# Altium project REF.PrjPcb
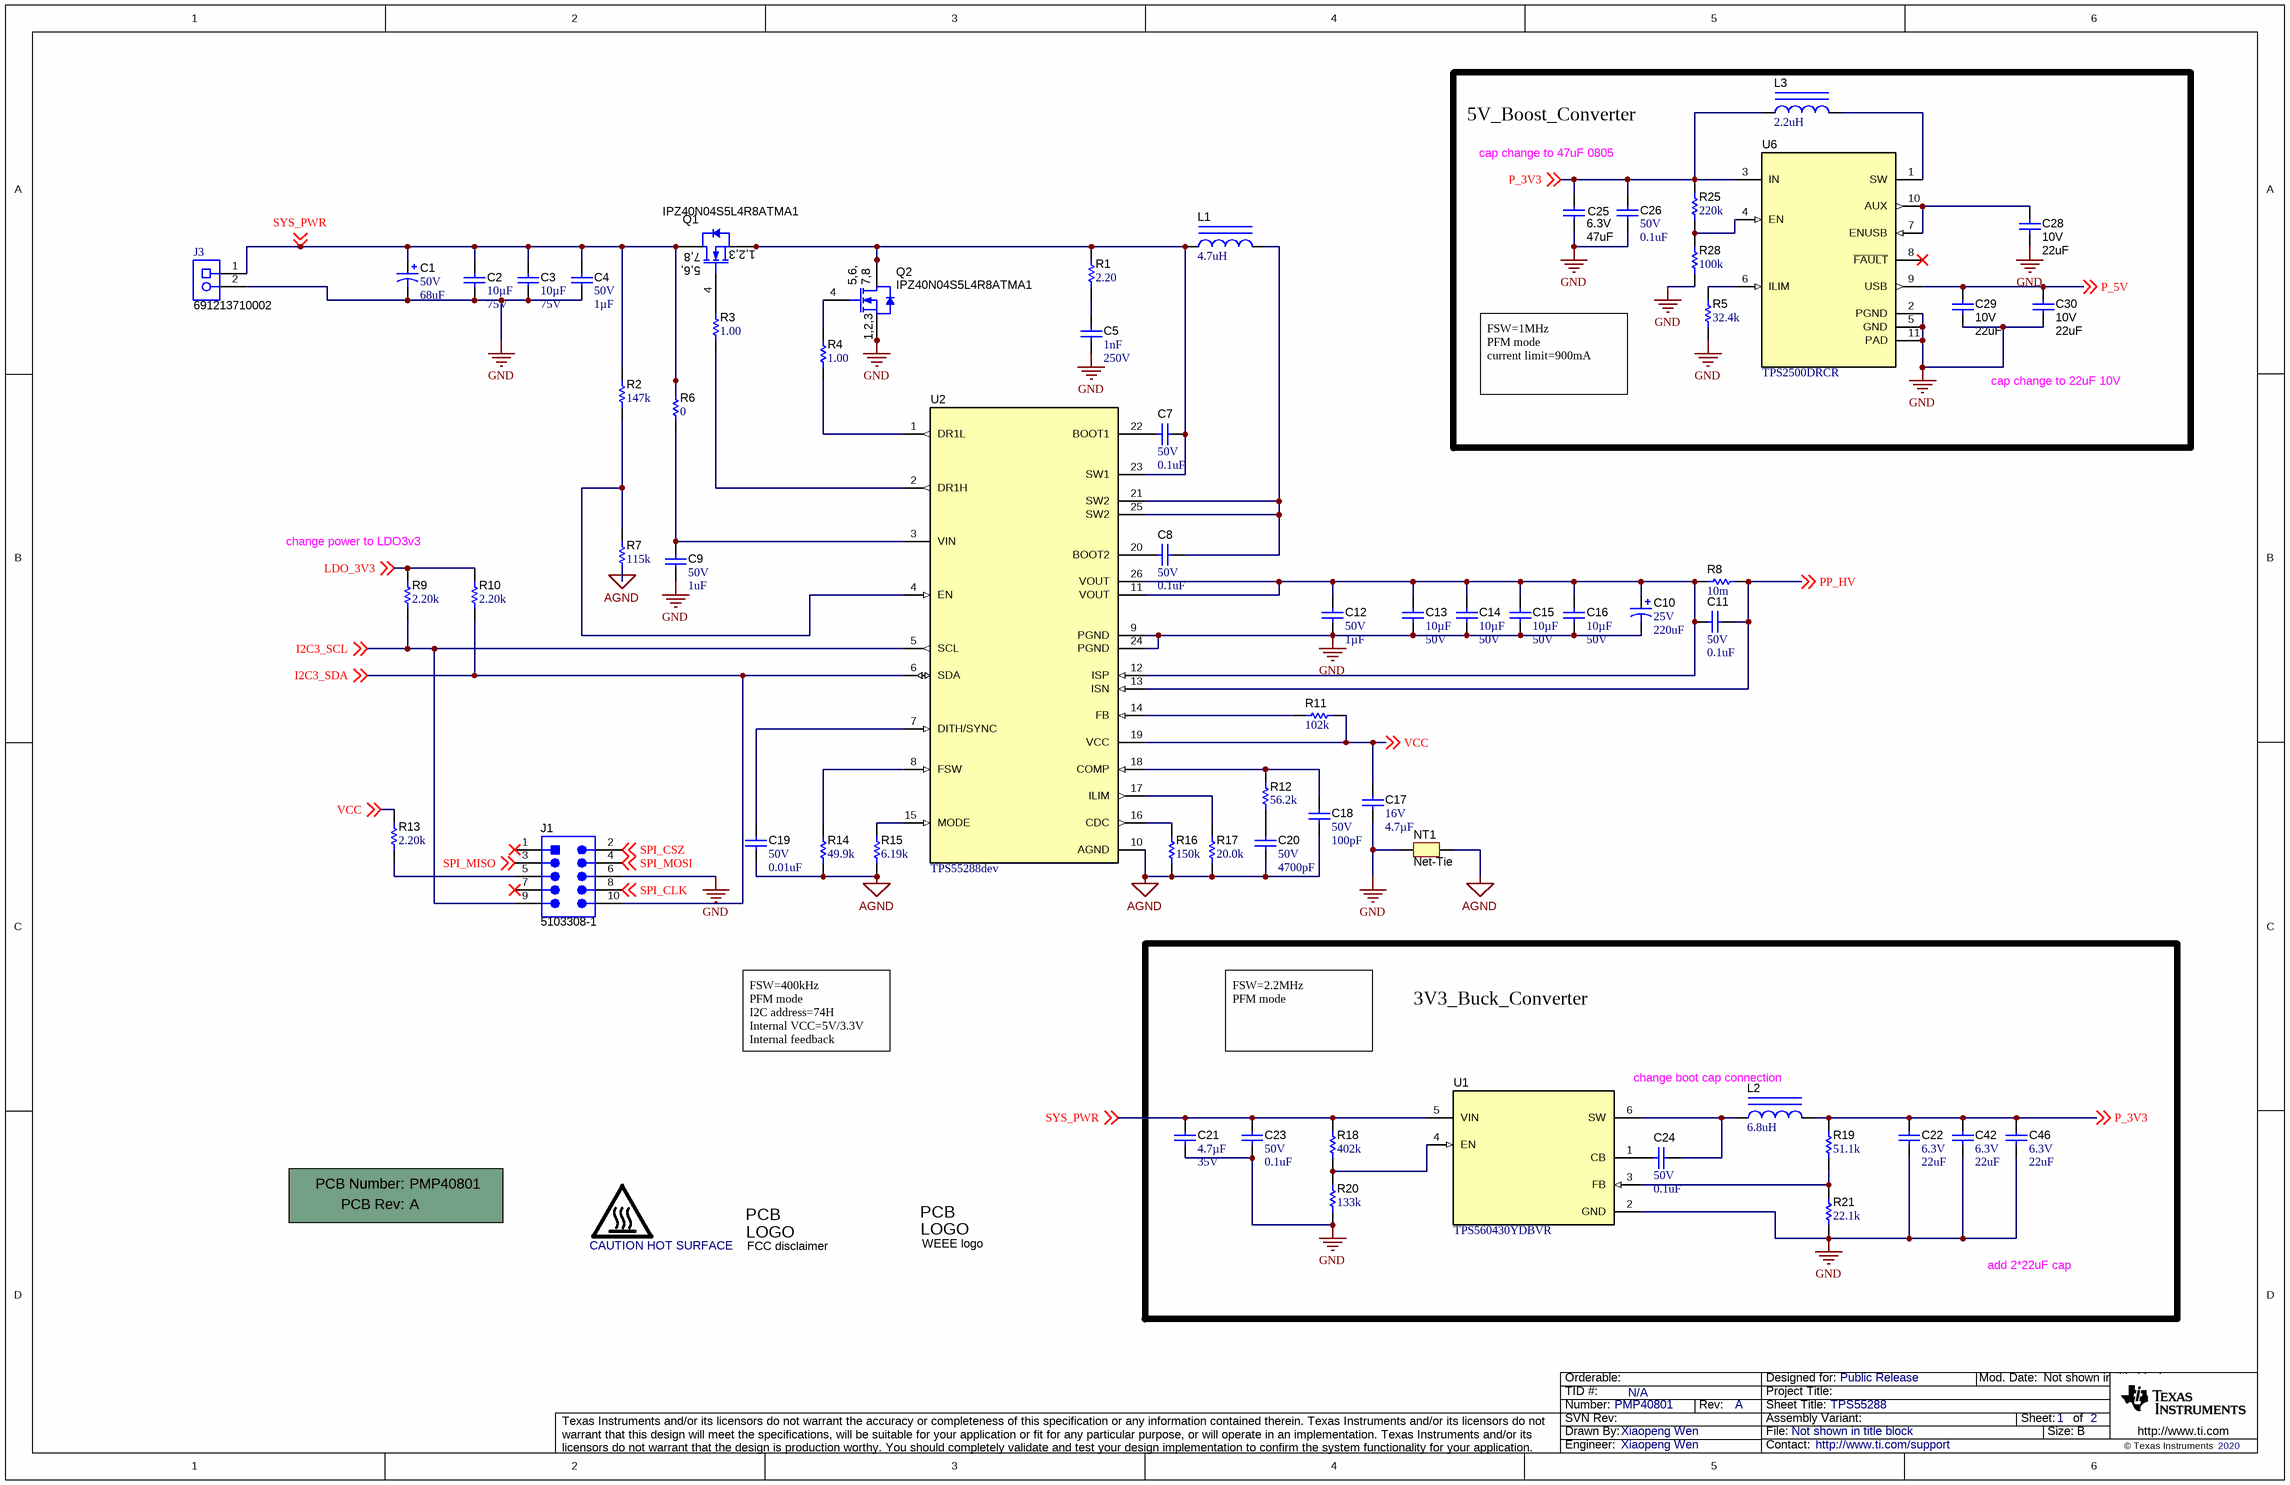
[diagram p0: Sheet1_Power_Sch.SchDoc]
TID: N/A; TechSupport: http://www.ti.com/support; SCH_Rev: A; PRJ_Number: PMP40801; PRJ_Engineer: Xiaopeng Wen; PRJ_Customer: Public Release; PCB_Rev: A; PCB_LayoutX: Xiaopeng Wen; CopyrightYear: 2020
2 sheets, 110 parts. Net scope: global (net labels, ports and power ports of the same name join across sheets).
Board file: REF0324.PcbDoc
Sheets:
  Sheet1_Power_Sch.SchDoc
  Sheet2_PD_Sch.SchDoc

## Sheet Sheet1_Power_Sch.SchDoc: TPS55288
size 431 x 279 mm; Date: Not shown in title block; ApprovedBy: Not shown in title block; CheckedBy: Not shown in title block; Author: Not shown in title block; CompanyName: Not shown in title block; DrawnBy: Xiaopeng Wen; Engineer: Not shown in title block; Organization: Not shown in title block; Address1: Not shown in title block; Address2: Not shown in title block; Address3: Not shown in title block; Address4: Not shown in title block; DocumentNumber: 1; Revision: Use project parameter SCH_Rev; SheetNumber: 1; SheetTotal: 2; PageSetup: Record=PageOptions¦CenterHorizontal=True¦CenterVertical=True¦PrintScale=1.00¦XCorrection=1.00¦YCorrection=1.00¦PrintKind=0¦BorderSize=5000000¦LeftOffset=0¦BottomOffset=0¦Orientation=2¦PaperLength=1000¦PaperWidth=1000¦Scale=100¦PaperSource=15¦PrintQuality=600¦MediaType=1¦DitherType=10¦PrintScaleMode=1¦PaperKind=Letter

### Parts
!PCB1  Printed Circuit Board  (value not drawn)  (mechanical)
C1  VDC_V: 50V  ValueDisplayed: 68uF  [SM_RADIAL_8MM]  (hidden comment: EEHZA1H680P)
C2  ValueDisplayed: 10µF  VDC_V: 75V  [1210_280]  (hidden comment: CGA6P1X7R1N106M250AC)
C3  ValueDisplayed: 10µF  VDC_V: 75V  [1210_280]  (hidden comment: CGA6P1X7R1N106M250AC)
C4  VDC_V: 50V  ValueDisplayed: 1µF  [0603]  (hidden comment: GRT188R61H105ME13D)
C5  Cap_F: 1nF  VDC_V: 250V  [0805_HV]  (hidden comment: GRM21AR72E222KW01D)
C7  VDC_V: 50V  ValueDisplayed: 0.1uF  [0402]  (hidden comment: CGA2B3X7R1H104K050BB)
C8  VDC_V: 50V  ValueDisplayed: 0.1uF  [0402]  (hidden comment: CGA2B3X7R1H104K050BB)
C9  VDC_V: 50V  ValueDisplayed: 1uF  [0402]  (hidden comment: CGA2B3X7R1H103K050BB)
C10  VDC_V: 25V  ValueDisplayed: 220uF  [SM_RADIAL_8MM]  (hidden comment: EEHZA1E221P)
C11  VDC_V: 50V  ValueDisplayed: 0.1uF  [0402]  (hidden comment: CGA2B3X7R1H104K050BB)
C12  VDC_V: 50V  ValueDisplayed: 1µF  [0603]  (hidden comment: GRT188R61H105ME13D)
C13  ValueDisplayed: 10µF  VDC_V: 50V  [1206_190]  (hidden comment: CGA5L1X7R1H106K160AC)
C14  ValueDisplayed: 10µF  VDC_V: 50V  [1206_190]  (hidden comment: CGA5L1X7R1H106K160AC)
C15  ValueDisplayed: 10µF  VDC_V: 50V  [1206_190]  (hidden comment: CGA5L1X7R1H106K160AC)
C16  ValueDisplayed: 10µF  VDC_V: 50V  [1206_190]  (hidden comment: CGA5L1X7R1H106K160AC)
C17  VDC_V: 16V  ValueDisplayed: 4.7µF  [0603]  (hidden comment: GRT188R61C475KE13D)
C18  VDC_V: 50V  ValueDisplayed: 100pF  [0402]  (hidden comment: CGA2B2C0G1H101J050BA)
C19  VDC_V: 50V  ValueDisplayed: 0.01uF  [0402]  (hidden comment: CGA2B3X7R1H103K050BB)
C20  VDC_V: 50V  ValueDisplayed: 4700pF  [0402]  (hidden comment: CGA2B2X7R1H472K050BA)
C21  Cap_F: 4.7µF  VDC_V: 35V  [0805_HV]  (hidden comment: C2012X7R1V475K125AC)
C22  VDC_V: 6.3V  ValueDisplayed: 22uF  [0805_HV]  (hidden comment: GRM21BD70J226ME44L)
C23  VDC_V: 50V  ValueDisplayed: 0.1uF  [0402]  (hidden comment: GCM155R71H104KE02D)
C24  VDC_V: 50V  ValueDisplayed: 0.1uF  [0402]  (hidden comment: GCM155R71H104KE02D)
C25  VDC_V: 6.3V  ValueDisplayed: 47uF  [0805L]  (hidden comment: GRM21BR60J476ME15L)
C26  VDC_V: 50V  ValueDisplayed: 0.1uF  [0402]  (hidden comment: GCM155R71H104KE02D)
C28  VDC_V: 10V  ValueDisplayed: 22uF  [0603]  (hidden comment: C1608X5R1A226M080AC)
C29  VDC_V: 10V  ValueDisplayed: 22uF  [0603]  (hidden comment: C1608X5R1A226M080AC)
C30  VDC_V: 10V  ValueDisplayed: 22uF  [0603]  (hidden comment: C1608X5R1A226M080AC)
C42  VDC_V: 6.3V  ValueDisplayed: 22uF  [0805_HV]  (hidden comment: GRM21BD70J226ME44L)
C46  VDC_V: 6.3V  ValueDisplayed: 22uF  [0805_HV]  (hidden comment: GRM21BD70J226ME44L)
J1  5103308-1  [CONN_5103308-1]
J3  691213710002  [Wurth_691213710002]
L1  ValueDisplayed: 4.7uH  [XAL1010]  (hidden comment: XAL1010-472MEB)
L2  ValueDisplayed: 6.8uH  [ME3220]  (hidden comment: ME3220-682MLB)
L3  ValueDisplayed: 2.2uH  [WE-MAIA_4020]  (hidden comment: 78438356022)
Logo1  FCC disclaimer  [FCC_disclaimer]  (no BOM)
Logo2  WEEE logo  [WEEE_Minimum]  (no BOM)
LOGO3  CAUTION HOT SURFACE  [IEC_HotSurface_Small]  (no BOM)
NT1  Net-Tie  [Net-Tie_10milWide_30milLong]  (net tie, no BOM)
Q1  IPZ40N04S5L4R8ATMA1  [PG-TSDSON-8-32]
Q2  IPZ40N04S5L4R8ATMA1  [PG-TSDSON-8-32]
R1  ValueDisplayed: 2.20  [1206]  (hidden comment: ERJ-8RQF2R2V)
R2  ValueDisplayed: 147k  [0402]  (hidden comment: CRCW0402100KFKED)
R3  ValueDisplayed: 1.00  [0402]  (hidden comment: CRCW06031R00FKEA)
R4  ValueDisplayed: 1.00  [0402]  (hidden comment: CRCW06031R00FKEA)
R5  ValueDisplayed: 32.4k  [0402]  (hidden comment: CRCW040232K4FKED)
R6  ValueDisplayed: 0  [0402]  (hidden comment: CRCW04020000Z0ED)
R7  ValueDisplayed: 115k  [0402]  (hidden comment: CRCW0402115KFKED)
R8  ValueDisplayed: 10m  [FP-CRF1206-FZ-R010ELF_1206-MFG]  (hidden comment: CRF1206-FZ-R010ELF)
R9  ValueDisplayed: 2.20k  [0402]  (hidden comment: CRCW04022K20FKED)
R10  ValueDisplayed: 2.20k  [0402]  (hidden comment: CRCW04022K20FKED)
R11  ValueDisplayed: 102k  [0402]  (hidden comment: CRCW0402102KFKED)
R12  ValueDisplayed: 56.2k  [0402]  (hidden comment: CRCW040256K2FKED)
R13  ValueDisplayed: 2.20k  [0402]  (hidden comment: CRCW04022K20FKED)
R14  ValueDisplayed: 49.9k  [0402]  (hidden comment: CRCW040249K9FKED)
R15  ValueDisplayed: 6.19k  [0402]  (hidden comment: CRCW04026K19FKED)
R16  ValueDisplayed: 150k  [0402]  (hidden comment: CRCW0402150KFKED)
R17  ValueDisplayed: 20.0k  [0402]  (hidden comment: CRCW040220K0FKED)
R18  ValueDisplayed: 402k  [0402]  (hidden comment: CRCW0402100KFKED)
R19  ValueDisplayed: 51.1k  [0402]  (hidden comment: CRCW040251K1FKED)
R20  ValueDisplayed: 133k  [0402]  (hidden comment: CRCW0402100KFKED)
R21  ValueDisplayed: 22.1k  [0402]  (hidden comment: CRCW040222K1FKED)
R25  ValueDisplayed: 220k  [0402]  (hidden comment: CRCW0402100KFKED)
R28  ValueDisplayed: 100k  [0402]  (hidden comment: CRCW0402100KFKED)
U1  TPS560430YDBVR  [DBV0006A_N]
U2  TPS55288dev  [RPM0026A]
U6  TPS2500DRCR  [DRC0010J]

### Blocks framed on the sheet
5V_Boost_Converter: C25 C26 C28-C30 L3 R5 R25 R28 U6
3V3_Buck_Converter: C21-C24 C42 C46 L2 R18-R21 U1

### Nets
AGND: C18.2 C19.2 C20.2 NT1.2 R7.1 R14.1 R15.1 R16.1 R17.1 U2.10(AGND)
GND: C1.2(-) C2.2 C3.2 C4.2 C5.2 C9.2 C10.2(-) C12.2 C13.2 C14.2 C15.2 C16.2 C17.2 C21.2 C22.2 C23.2 C25.2 C26.2 C28.2 C29.2 C30.2 C42.2 C46.2 J1.6 J3.2 NT1.1 Q2.1(S) Q2.2(S) Q2.3(S) R5.1 R20.1 R21.1 R28.1 U1.2(GND) U2.9(PGND) U2.24(PGND) U6.2(PGND) U6.5(GND) U6.11(PAD)
I2C3_SCL: J1.9 R9.1 U2.5(SCL) ; off-sheet I2C3_SCL
I2C3_SDA: J1.10 R10.1 U2.6(SDA) ; off-sheet I2C3_SDA
LDO_3V3: R9.2 R10.2 ; off-sheet LDO_3V3
P_3V3: C22.1 C25.1 C26.1 C42.1 C46.1 L2.2 L3.1 R19.2 R25.2 U6.3(IN) ; off-sheet P_3V3
P_5V: C29.1 C30.1 U6.9(USB) ; off-sheet P_5V
PP_HV: C11.2 R8.2 U2.13(ISN) ; off-sheet PP_HV
SPI_CLK: J1.8 ; off-sheet SPI_CLK
SPI_CSZ: J1.2 ; off-sheet SPI_CSZ
SPI_MISO: J1.3 ; off-sheet SPI_MISO
SPI_MOSI: J1.4 ; off-sheet SPI_MOSI
SYS_PWR: C1.1(+) C2.1 C3.1 C4.1 C21.1 C23.1 J3.1 Q1.5(D) Q1.6(D) Q1.7(D) Q1.8(D) Q1.9(D) R2.2 R6.2 R18.2 U1.5(VIN) ; off-sheet SYS_PWR
VCC: C17.1 R11.1 R13.2 U2.19(VCC) ; off-sheet VCC
NetC5_1: C5.1 R1.1
NetC7_1: C7.1 U2.22(BOOT1)
NetC7_2: C7.2 L1.1 Q1.1(S) Q1.2(S) Q1.3(S) Q2.5(D) Q2.6(D) Q2.7(D) Q2.8(D) Q2.9(D) R1.2 U2.23(SW1)
NetC8_1: C8.1 U2.20(BOOT2)
NetC8_2: C8.2 L1.2 U2.21(SW2) U2.25(SW2)
NetC9_1: C9.1 R6.1 U2.3(VIN)
NetC10_1: C10.1(+) C11.1 C12.1 C13.1 C14.1 C15.1 C16.1 R8.1 U2.11(VOUT) U2.12(ISP) U2.26(VOUT)
NetC18_1: C18.1 R12.2 U2.18(COMP)
NetC19_1: C19.1 U2.7(DITH/SYNC)
NetC20_1: C20.1 R12.1
NetC24_1: C24.1 U1.1(CB)
NetC24_2: C24.2 L2.1 U1.6(SW)
NetC28_1: C28.1 U6.7(ENUSB) U6.10(AUX)
NetJ1_5: J1.5 R13.1
NetL3_2: L3.2 U6.1(SW)
NetQ1_4: Q1.4(G) R3.2
NetQ2_4: Q2.4(G) R4.2
NetR2_1: R2.1 R7.2 U2.4(EN)
NetR3_1: R3.1 U2.2(DR1H)
NetR4_1: R4.1 U2.1(DR1L)
NetR5_2: R5.2 U6.6(ILIM)
NetR11_2: R11.2 U2.14(FB)
NetR14_2: R14.2 U2.8(FSW)
NetR15_2: R15.2 U2.15(MODE)
NetR16_2: R16.2 U2.16(CDC)
NetR17_2: R17.2 U2.17(ILIM)
NetR18_1: R18.1 R20.2 U1.4(EN)
NetR19_1: R19.1 R21.2 U1.3(FB)
NetR25_1: R25.1 R28.2 U6.4(EN)

Not connected (* = marked no-connect by the designer): J1 1* 7*; U6 8(~{FAULT})*

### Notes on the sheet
- cap change to 47uF 0805
- FSW=1MHz
  PFM mode
  current limit=900mA
- cap change to 22uF 10V
- (near R9) change power to LDO3v3
- FSW=400kHz
  PFM mode
  I2C address=74H
  Internal VCC=5V/3.3V
  Internal feedback
- FSW=2.2MHz
  PFM mode
- change boot cap connection
- add 2*22uF cap

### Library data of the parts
!PCB1 = CMP-0003618-2: Manufacturer: Any; PartNumber: PMP40801
C1 = CMP-0012579-3: CAP, Polymer Hybrid, 68 uF, 50 V, +/- 20%, 30 ohm, 8x10 SMD; Manufacturer: Panasonic; TaMin_C: -55°C; ESR_ohm: 30; Polarized: Y; SizeAreaWB_mm2: 113.3; Value1: 30 ohm; Value: 68uF; TaMax_C: 105°C; SizeZ_mm: 10.2; SizeX_mm: 9; SizeY_mm: 8.3; SizeArea_mm2: 74.7; CompType: Capacitor; Cap_F: 68µF; IRMS_A: 1.8A; AEC Category: Q200
C2 C3 = CMP-0085951-1: CAP, CERM, 10 µF, 75 V,+/- 20%, X7R, AEC-Q200 Grade 1, 1210; Manufacturer: TDK; SizeX_mm: 3.2; Cap_Case: 1210; AEC Qualified: Y; Polarized: N; AEC Category: Q200; U/M: EA; SizeZ_mm: 2.8; SizeY_mm: 2.5; TaMin_C: -55°C; AEC Grade: 1; SizeAreaWB_mm2: 14.7; SizeArea_mm2: 8; TaMax_C: 125°C; Value: 10uF
C4 C12 = CMP-0081784-1: CAP, CERM, 1 µF, 50 V,+/- 20%, X5R, AEC-Q200 Grade 3, 0603; Manufacturer: MuRata; TaMin_C: -55°C; Polarized: N; SizeAreaWB_mm2: 4.68; U/M: EA; Value: 1uF; TaMax_C: 85°C; SizeZ_mm: 1; SizeX_mm: 1.6; SizeY_mm: 0.8; SizeArea_mm2: 1.28; AEC Qualified: Y; AEC Grade: 3; AEC Category: Q200
C5 = CMP-0008253-2: CAP, CERM, 2200 pF, 250 V, +/- 10%, X7R, 0805; Manufacturer: MuRata; TaMin_C: -55°C; Polarized: N; SizeAreaWB_mm2: 6.75; Value1: Unknown; U/M: EA; Value: 2200pF; TaMax_C: 125°C; SizeZ_mm: 1.45; SizeX_mm: 2; SizeY_mm: 1.25; Cap_Case: 0805; SizeArea_mm2: 2.5; CompType: Capacitor; AEC Category: Q200
C7 C8 C11 = CMP-0006325-2: CAP, CERM, 0.1 uF, 50 V, +/- 10%, X7R, AEC-Q200 Grade 1, 0402; Manufacturer: TDK; TaMin_C: -55°C; ESR_ohm: 0.039064; Polarized: N; SizeAreaWB_mm2: 3; Value1: 0.039064 ohm; U/M: EA; Value: 0.1uF; TaMax_C: 125°C; SizeZ_mm: 0.6; SizeX_mm: 1; SizeY_mm: 0.5; AEC Qualified: Y; Cap_F: 100nF; IRMS_A: 8.14669dA; AEC Category: Q200
C9 = CMP-0006324-2: CAP, CERM, 1 uF, 50 V, +/- 10%, X7R, AEC-Q200 Grade 1, 0402; Manufacturer: TDK; TaMin_C: -55°C; ESR_ohm: 3.33065d; Polarized: N; SizeAreaWB_mm2: 3; Value1: 0.333065 ohm; U/M: EA; Value: 1uF; TaMax_C: 125°C; SizeZ_mm: 0.6; SizeX_mm: 1; SizeY_mm: 0.5; CompType: Capacitor; AEC Qualified: Y; Cap_F: 10nF; IRMS_A: 3.23373dA; AEC Category: Q200
C10 = CMP-0012571-3: CAP, Polymer Hybrid, 220 uF, 25 V, +/- 20%, 27 ohm, 8x10 SMD; Manufacturer: Panasonic; TaMin_C: -55°C; ESR_ohm: 27; Polarized: Y; SizeAreaWB_mm2: 113.3; Value1: 27 ohm; Value: 220uF; TaMax_C: 105°C; SizeZ_mm: 10.2; SizeX_mm: 9; SizeY_mm: 8.3; SizeArea_mm2: 74.7; CompType: Capacitor; Cap_F: 220µF; IRMS_A: 2.3A; AEC Category: Q200
C13-C16 = CMP-0085950-1: CAP, CERM, 10 µF, 50 V,+/- 10%, X7R, AEC-Q200 Grade 1, 1206; Manufacturer: TDK; SizeZ_mm: 1.9; Value: 10uF; Cap_Case: 1206; AEC Grade: 1; TaMin_C: -55°C; U/M: EA; SizeArea_mm2: 5.12; TaMax_C: 125°C; AEC Qualified: Y; AEC Category: Q200; SizeX_mm: 3.2; SizeY_mm: 1.6; Polarized: N; SizeAreaWB_mm2: 10.92
C17 = CMP-0081052-1: CAP, CERM, 4.7 µF, 16 V,+/- 10%, X5R, AEC-Q200 Grade 3, 0603; Manufacturer: MuRata; SizeAreaWB_mm2: 4.68; SizeArea_mm2: 1.28; AEC Qualified: Y; AEC Category: Q200; Value: 4.7uF; TaMax_C: 85°C; SizeZ_mm: 1; AEC Grade: 3; Polarized: N; TaMin_C: -55°C; SizeY_mm: 0.8; U/M: EA; SizeX_mm: 1.6
C18 = CMP-0006308-2: CAP, CERM, 100 pF, 50 V, +/- 5%, C0G/NP0, AEC-Q200 Grade 1, 0402; Manufacturer: TDK; TaMin_C: -55°C; Polarized: N; SizeAreaWB_mm2: 3; Value1: Unknown; U/M: EA; Value: 100pF; TaMax_C: 125°C; SizeZ_mm: 0.6; SizeX_mm: 1; SizeY_mm: 0.5; AEC Qualified: Y; AEC Category: Q200
C19 = CMP-0006324-2: CAP, CERM, 0.01 uF, 50 V, +/- 10%, X7R, AEC-Q200 Grade 1, 0402; Manufacturer: TDK; TaMin_C: -55°C; ESR_ohm: 3.33065d; Polarized: N; SizeAreaWB_mm2: 3; Value1: 0.333065 ohm; U/M: EA; Value: 0.01uF; TaMax_C: 125°C; SizeZ_mm: 0.6; SizeX_mm: 1; SizeY_mm: 0.5; AEC Qualified: Y; Cap_F: 10nF; IRMS_A: 3.23373dA; AEC Category: Q200
C20 = CMP-0006321-2: CAP, CERM, 4700 pF, 50 V, +/- 10%, X7R, AEC-Q200 Grade 1, 0402; Manufacturer: TDK; TaMin_C: -55°C; ESR_ohm: 4.13508d; Polarized: N; SizeAreaWB_mm2: 3; Value1: 0.413508 ohm; U/M: EA; Value: 4700pF; TaMax_C: 125°C; SizeZ_mm: 0.6; SizeX_mm: 1; SizeY_mm: 0.5; AEC Qualified: Y; Cap_F: 4.7nF; IRMS_A: 3.30878dA; AEC Category: Q200
C21 = CMP-0007885-2: CAP, CERM, 4.7 uF, 35 V, +/- 10%, X7R, 0805; Manufacturer: TDK; TaMin_C: -55°C; ESR_ohm: 2.346m; Polarized: N; SizeAreaWB_mm2: 6.75; Value1: 0.002346 ohm; U/M: EA; Value: 4.7uF; TaMax_C: 125°C; SizeZ_mm: 1.45; SizeX_mm: 2; SizeY_mm: 1.25; Cap_Case: 0805; SizeArea_mm2: 2.5; IRMS_A: 4.26021A; AEC Category: Q200
C22 C42 C46 = CMP-0008274-1: CAP, CERM, 22 uF, 6.3 V, +/- 20%, X7T, 0805; Manufacturer: MuRata; TaMin_C: -55°C; Polarized: N; SizeAreaWB_mm2: 6.75; Value1: Unknown; U/M: EA; Value: 22uF; TaMax_C: 125°C; SizeZ_mm: 1.45; SizeX_mm: 2; SizeY_mm: 1.25; Cap_Case: 0805; SizeArea_mm2: 2.5; Cap_F: 22µF; AEC Category: Q200
C23 C24 C26 = CMP-0006356-2: CAP, CERM, 0.1 uF, 50 V, +/- 10%, X7R, AEC-Q200 Grade 1, 0402; Manufacturer: MuRata; TaMin_C: -55°C; Polarized: N; SizeAreaWB_mm2: 3; Value1: Unknown; U/M: EA; Value: 0.1uF; TaMax_C: 125°C; SizeZ_mm: 0.6; SizeX_mm: 1; SizeY_mm: 0.5; AEC Qualified: Y; Cap_F: 100nF; AEC Category: Q200
C25 = CMP-0008284-1: CAP, CERM, 47 uF, 6.3 V, +/- 20%, X5R, 0805; Manufacturer: MuRata; TaMin_C: -55°C; Polarized: N; SizeAreaWB_mm2: 6.75; Value1: Unknown; U/M: EA; Value: 47uF; TaMax_C: 85°C; SizeZ_mm: 1.45; SizeX_mm: 2; SizeY_mm: 1.25; Cap_Case: 0805; SizeArea_mm2: 2.5; Cap_F: 47µF; AEC Category: Q200
C28-C30 = CMP-0007005-5: CAP, CERM, 22 uF, 10 V, +/- 20%, X5R, 0603; Manufacturer: TDK; TaMin_C: -55°C; Polarized: N; SizeAreaWB_mm2: 4.68; Value1: 0.00371 ohm; U/M: EA; Value: 22uF; TaMax_C: 85°C; SizeZ_mm: 1; SizeX_mm: 1.6; SizeY_mm: 0.8; SizeArea_mm2: 1.28; Cap_F: 22µF; AEC Category: Q200; ESR_ohm: 3.71m; IRMS_A: 2.69936A
J1 = CMP-0054834-2: Header (shrouded), 100mil, 5x2, Gold, TH; Manufacturer: TE Connectivity; Green_Lifecycle: Active; Green_REACh: Passed
J3 = CMP-0054823-2: Terminal Block, 2x1, Brass, TH; Manufacturer: Wurth Elektronik; CT: TRUE; Gender: Female; Green_Lifecycle: Active; CNHeader: FALSE; Pitch_mm: 5; Green_REACh: Passed; Row_Count: 1
L1 = CMP-0060950-1: Inductor, Shielded, Composite, 4.7 uH, 24 A, 0.01 ohm, SMD; Manufacturer: Coilcraft; Isat: 25.4A @ 30% inductance drop; Green_Lifecycle: Not Set; SizeAreaWB_mm2: 159.6; DCR_ohm: 0.01; Green_REACh: Incomplete; Irms: 24A @ 40C rise; Value: 4.7uH; Imax_A: 24A; SizeZ_mm: 10; SizeX_mm: 11.3; SizeArea_mm2: 113; Ind_H: 4.7µH; AEC Category: Q200
L2 = CMP-0060543-1: Inductor, Drum Core, Ferrite, 6.8 uH, 1.1 A, 0.27 ohm, SMD; Manufacturer: Coilcraft; Isat: 1.2A @ 30% inductance drop; Irms: 1.1A @ 40C rise; Green_Lifecycle: Not Set; SizeAreaWB_mm2: 15.96; DCR_ohm: 2.7d; Green_REACh: Incomplete; Value: 6.8uH; Imax_A: 1.1A; SizeZ_mm: 2; SizeX_mm: 3.2; SizeY_mm: 2.8; SizeArea_mm2: 8.96; Ind_H: 6.8µH; AEC Category: Q200
L3 = CMP-0064366-1: Inductor, Shielded, Powdered Iron, 2.2 uH, 4.7 A, 0.035 ohm, AEC-Q200 Grade 1, SMD; Manufacturer: Wurth Elektronik; Isat: 6.2A @ 20% inductance drop; Irms: 4.7A @ 40C rise; SizeAreaWB_mm2: 26.01; DCR_ohm: 0.035; Value: 2.2uH; Imax_A: 4.7A; SizeZ_mm: 2.1; SizeX_mm: 4.1; SizeArea_mm2: 16.81; Ind_H: 2.2µH; AEC Qualified: Y; AEC Grade: 1; AEC Category: Q200
Logo1 = CMP-0074847-1: FCC_disclaimer; Library Reference: Logo
Logo2 = CMP-0074769-1
LOGO3 = CMP-0074837-1: IEC 61010-1 Hot Surface Warning; SymbolCreator: a0412235
NT1 = CMP-0078142-3: Single point connection between nets.
Q1 Q2 = CMP-0080660-1: MOSFET, N-CH, 40 V, 40 A, AEC-Q101, SON-8; Alternate Manufacturer: None; Manufacturer: Infineon Technologies; Rdson45_ohm: 6.7m; QgTyp_nC: 22; SizeAreaWB_mm2: 18.49; Vgs_V: 16V; Value1: 0.0067 ohm; VdsMax_V: 40V; Value: 40V; IdsMax_A: 40A; SizeZ_mm: 1.15; SizeX_mm: 3.3; Value2: 22 nC; SizeArea_mm2: 10.89; ChType: N; AEC Qualified: Y; AEC Category: Q101
R1 = CMP-0017777-3: RES, 2.20, 1%, 0.25 W, AEC-Q200 Grade 0, 1206; Manufacturer: Panasonic; Power_W: 250mW; TempCo: 200 ppm/C; Value_Code: 2R20; Value: 2.20; Res_ohm: 2.2; SizeX_mm: 3.2; SizeY_mm: 1.6; SizeZ_mm: 1.35; Value2: 0.25W; SizeArea_mm2: 5.12; AEC Qualified: Y; AEC Category: Q200; AEC Grade: 0; SizeAreaWB_mm2: 10.92
R2 = CMP-0025950-3: RES, 100 k, 1%, 0.063 W, AEC-Q200 Grade 0, 0402; Manufacturer: Vishay-Dale; Power_W: 63mW; TempCo: 100 ppm/C; Value: 147k; EIA_Code: E96; Res_ohm: 100k; SizeX_mm: 1; SizeY_mm: 0.5; SizeZ_mm: 0.6; Value2: 0.063W; CompType: Resistor; AEC Qualified: Y; VDC_V: 50V; AEC Category: Q200; AEC Grade: 0
R3 = CMP-0022170-4: RES, 1.00, 1%, 0.1 W, AEC-Q200 Grade 0, 0603; Manufacturer: Vishay-Dale; Power_W: 100mW; TempCo: 100 ppm/C; Value_Code: 1R00; Value: 1.00; EIA_Code: E96; Res_ohm: 1; SizeX_mm: 1.6; SizeY_mm: 0.8; Value2: 0.1W; SizeArea_mm2: 1.28; CompType: Resistor; AEC Qualified: Y; VDC_V: 75V; AEC Category: Q200; AEC Grade: 0
R4 = CMP-0022170-4: RES, 1.00, 1%, 0.1 W, AEC-Q200 Grade 0, 0603; Manufacturer: Vishay-Dale; Power_W: 100mW; TempCo: 100 ppm/C; Value_Code: 1R00; Value: 1.00; EIA_Code: E96; Res_ohm: 1; SizeX_mm: 1.6; SizeY_mm: 0.8; Value2: 0.1W; SizeArea_mm2: 1.28; AEC Qualified: Y; VDC_V: 75V; AEC Category: Q200; AEC Grade: 0
R5 = CMP-0026294-2: RES, 32.4 k, 1%, 0.063 W, AEC-Q200 Grade 0, 0402; Manufacturer: Vishay-Dale; Power_W: 63mW; TempCo: 100 ppm/C; Value_Code: 32k4; Value: 32.4k; EIA_Code: E96; SizeX_mm: 1; SizeY_mm: 0.5; SizeZ_mm: 0.6; Value2: 0.063W; AEC Qualified: Y; VDC_V: 50V; AEC Category: Q200; AEC Grade: 0
R6 = CMP-0026822-3: RES, 0, 5%, 0.063 W, AEC-Q200 Grade 0, 0402; Manufacturer: Vishay-Dale; Power_W: 63mW; TempCo: 200 ppm/C; Value_Code: 0000; Value: 0; EIA_Code: E24; SizeX_mm: 1; SizeY_mm: 0.5; SizeZ_mm: 0.6; Value2: 0.063W; AEC Qualified: Y; VDC_V: 50V; AEC Category: Q200
R7 = CMP-0025971-3: RES, 115 k, 1%, 0.063 W, AEC-Q200 Grade 0, 0402; Manufacturer: Vishay-Dale; Power_W: 63mW; TempCo: 100 ppm/C; Value: 115k; EIA_Code: E96; SizeX_mm: 1; SizeY_mm: 0.5; SizeZ_mm: 0.6; Value2: 0.063W; AEC Qualified: Y; VDC_V: 50V; AEC Category: Q200; AEC Grade: 0
R8 = CMP-0086941-2: 10 mOhms ±1% 1W Chip Resistor 1206 (3216 Metric) Automotive AEC-Q200, Current Sense, Moisture Resistant Metal Element; Manufacturer: Bourns; AEC Qualified: Yes; TempCo: 50ppm/°C; AEC Grade: Grade 0; Res_ohm: 0.01; SizeZ_mm: 0.8mm
R9 R10 R13 = CMP-0026231-2: RES, 2.20 k, 1%, 0.063 W, AEC-Q200 Grade 0, 0402; Manufacturer: Vishay-Dale; Power_W: 63mW; TempCo: 100 ppm/C; Value_Code: 2k20; Value: 2.20k; Res_ohm: 2.2k; SizeX_mm: 1; SizeY_mm: 0.5; SizeZ_mm: 0.6; Value2: 0.063W; AEC Qualified: Y; AEC Category: Q200; AEC Grade: 0
R11 = CMP-0025952-3: RES, 102 k, 1%, 0.063 W, AEC-Q200 Grade 0, 0402; Manufacturer: Vishay-Dale; Power_W: 63mW; TempCo: 100 ppm/C; Value: 102k; EIA_Code: E96; SizeX_mm: 1; SizeY_mm: 0.5; SizeZ_mm: 0.6; Value2: 0.063W; AEC Qualified: Y; VDC_V: 50V; AEC Category: Q200; AEC Grade: 0
R12 = CMP-0026453-2: RES, 56.2 k, 1%, 0.063 W, AEC-Q200 Grade 0, 0402; Manufacturer: Vishay-Dale; Power_W: 63mW; TempCo: 100 ppm/C; Value_Code: 56k2; Value: 56.2k; EIA_Code: E96; SizeX_mm: 1; SizeY_mm: 0.5; SizeZ_mm: 0.6; Value2: 0.063W; AEC Qualified: Y; VDC_V: 50V; AEC Category: Q200; AEC Grade: 0
R14 = CMP-0026403-2: RES, 49.9 k, 1%, 0.063 W, AEC-Q200 Grade 0, 0402; Manufacturer: Vishay-Dale; Power_W: 63mW; TempCo: 100 ppm/C; Value_Code: 49k9; Value: 49.9k; EIA_Code: E96; SizeX_mm: 1; SizeY_mm: 0.5; SizeZ_mm: 0.6; Value2: 0.063W; AEC Qualified: Y; VDC_V: 50V; AEC Category: Q200; AEC Grade: 0
R15 = CMP-0026513-2: RES, 6.19 k, 1%, 0.063 W, AEC-Q200 Grade 0, 0402; Manufacturer: Vishay-Dale; Power_W: 63mW; TempCo: 100 ppm/C; Value_Code: 6k19; Value: 6.19k; EIA_Code: E96; SizeX_mm: 1; SizeY_mm: 0.5; SizeZ_mm: 0.6; Value2: 0.063W; CompType: Resistor; AEC Qualified: Y; VDC_V: 50V; AEC Category: Q200; AEC Grade: 0
R16 = CMP-0026021-3: RES, 150 k, 1%, 0.063 W, AEC-Q200 Grade 0, 0402; Manufacturer: Vishay-Dale; Power_W: 63mW; TempCo: 100 ppm/C; Value: 150k; EIA_Code: E96; SizeX_mm: 1; SizeY_mm: 0.5; SizeZ_mm: 0.6; Value2: 0.063W; AEC Qualified: Y; VDC_V: 50V; AEC Category: Q200; AEC Grade: 0
R17 = CMP-0026162-2: RES, 20.0 k, 1%, 0.063 W, AEC-Q200 Grade 0, 0402; Manufacturer: Vishay-Dale; Power_W: 63mW; TempCo: 100 ppm/C; Value_Code: 20k0; Value: 20.0k; EIA_Code: E96; Res_ohm: 20k; SizeX_mm: 1; SizeY_mm: 0.5; SizeZ_mm: 0.6; Value2: 0.063W; AEC Qualified: Y; VDC_V: 50V; AEC Category: Q200; AEC Grade: 0
R18 = CMP-0025950-3: RES, 100 k, 1%, 0.063 W, AEC-Q200 Grade 0, 0402; Manufacturer: Vishay-Dale; Power_W: 63mW; TempCo: 100 ppm/C; Value: 402k; EIA_Code: E96; Res_ohm: 100k; SizeX_mm: 1; SizeY_mm: 0.5; SizeZ_mm: 0.6; Value2: 0.063W; CompType: Resistor; AEC Qualified: Y; VDC_V: 50V; AEC Category: Q200; AEC Grade: 0
R19 = CMP-0026437-2: RES, 51.1 k, 1%, 0.063 W, AEC-Q200 Grade 0, 0402; Manufacturer: Vishay-Dale; Power_W: 63mW; TempCo: 100 ppm/C; Value_Code: 51k1; Value: 51.1k; EIA_Code: E96; SizeX_mm: 1; SizeY_mm: 0.5; SizeZ_mm: 0.6; Value2: 0.063W; AEC Qualified: Y; VDC_V: 50V; AEC Category: Q200; AEC Grade: 0
R20 = CMP-0025950-3: RES, 100 k, 1%, 0.063 W, AEC-Q200 Grade 0, 0402; Manufacturer: Vishay-Dale; Power_W: 63mW; TempCo: 100 ppm/C; Value: 133k; EIA_Code: E96; Res_ohm: 100k; SizeX_mm: 1; SizeY_mm: 0.5; SizeZ_mm: 0.6; Value2: 0.063W; CompType: Resistor; AEC Qualified: Y; VDC_V: 50V; AEC Category: Q200; AEC Grade: 0
R21 = CMP-0026178-2: RES, 22.1 k, 1%, 0.063 W, AEC-Q200 Grade 0, 0402; Manufacturer: Vishay-Dale; Power_W: 63mW; TempCo: 100 ppm/C; Value_Code: 22k1; Value: 22.1k; EIA_Code: E96; SizeX_mm: 1; SizeY_mm: 0.5; SizeZ_mm: 0.6; Value2: 0.063W; AEC Qualified: Y; VDC_V: 50V; AEC Category: Q200; AEC Grade: 0
R25 = CMP-0025950-3: RES, 100 k, 1%, 0.063 W, AEC-Q200 Grade 0, 0402; Manufacturer: Vishay-Dale; Power_W: 63mW; TempCo: 100 ppm/C; Value: 220k; EIA_Code: E96; SizeX_mm: 1; SizeY_mm: 0.5; SizeZ_mm: 0.6; Value2: 0.063W; CompType: Resistor; AEC Qualified: Y; VDC_V: 50V; AEC Category: Q200; AEC Grade: 0
R28 = CMP-0025950-3: RES, 100 k, 1%, 0.063 W, AEC-Q200 Grade 0, 0402; Manufacturer: Vishay-Dale; Power_W: 63mW; TempCo: 100 ppm/C; Value: 100k; EIA_Code: E96; SizeX_mm: 1; SizeY_mm: 0.5; SizeZ_mm: 0.6; Value2: 0.063W; CompType: Resistor; AEC Qualified: Y; VDC_V: 50V; AEC Category: Q200; AEC Grade: 0
U1 = CMP-0065101-3: 4V to 36 V 0.6 A Synchronous Step-Down Converter, DBV0006A (SOT-23-6); Manufacturer: Texas Instruments; Alternate PartNumber: TPS560430YDBVT; SizeX_mm: 2.8; SizeY_mm: 2.9; CompType: IC; SizeZ_mm: 1.45; SizeArea_mm2: 8.12; SizeAreaWB_mm2: 14.82; U/M: EA
U2 = CMP-0085347-3: 36-V, 16-A Buck-Boost Converter, RPM0026A (VQFN-HR-26); Manufacturer: Texas Instruments; AEC Category: Q200; SizeX_mm: 4; SizeAreaWB_mm2: 22.5; AEC Qualified: N; SizeY_mm: 3.5; SizeArea_mm2: 14; SizeZ_mm: 1; CompType: IC
U6 = CMP-0034518-5: Integrated USB Power Switch with Boost Converter, DRC0010J (VSON-10); Manufacturer: Texas Instruments; Current Limit Topology: Constant-Current; Rating: 0; Vin(Min)(V): 1.8; SizeArea_mm2: 9; Enable: Active High; Number of Switches: 1; SizeY_mm: 3; Vin(Max)(V): 5.25; Current Limit(A): 0.13 to 1.4; Continuous Current(Max)(A): 1.4; CompType: IC; AEC Category: Q200; SizeAreaWB_mm2: 16; AEC Qualified: N

## Sheet Sheet2_PD_Sch.SchDoc: TPS65987D
size 431 x 304 mm; SheetNumber: 2; PageSetup: Record=PageOptions¦CenterHorizontal=True¦CenterVertical=True¦PrintScale=1.00¦XCorrection=1.00¦YCorrection=1.00¦PrintKind=0¦BorderSize=5000000¦LeftOffset=0¦BottomOffset=0¦Orientation=2¦PaperLength=1000¦PaperWidth=1000¦Scale=100¦PaperSource=15¦PrintQuality=600¦MediaType=1¦DitherType=10¦PaperKind=Letter¦PrintScaleMode=1
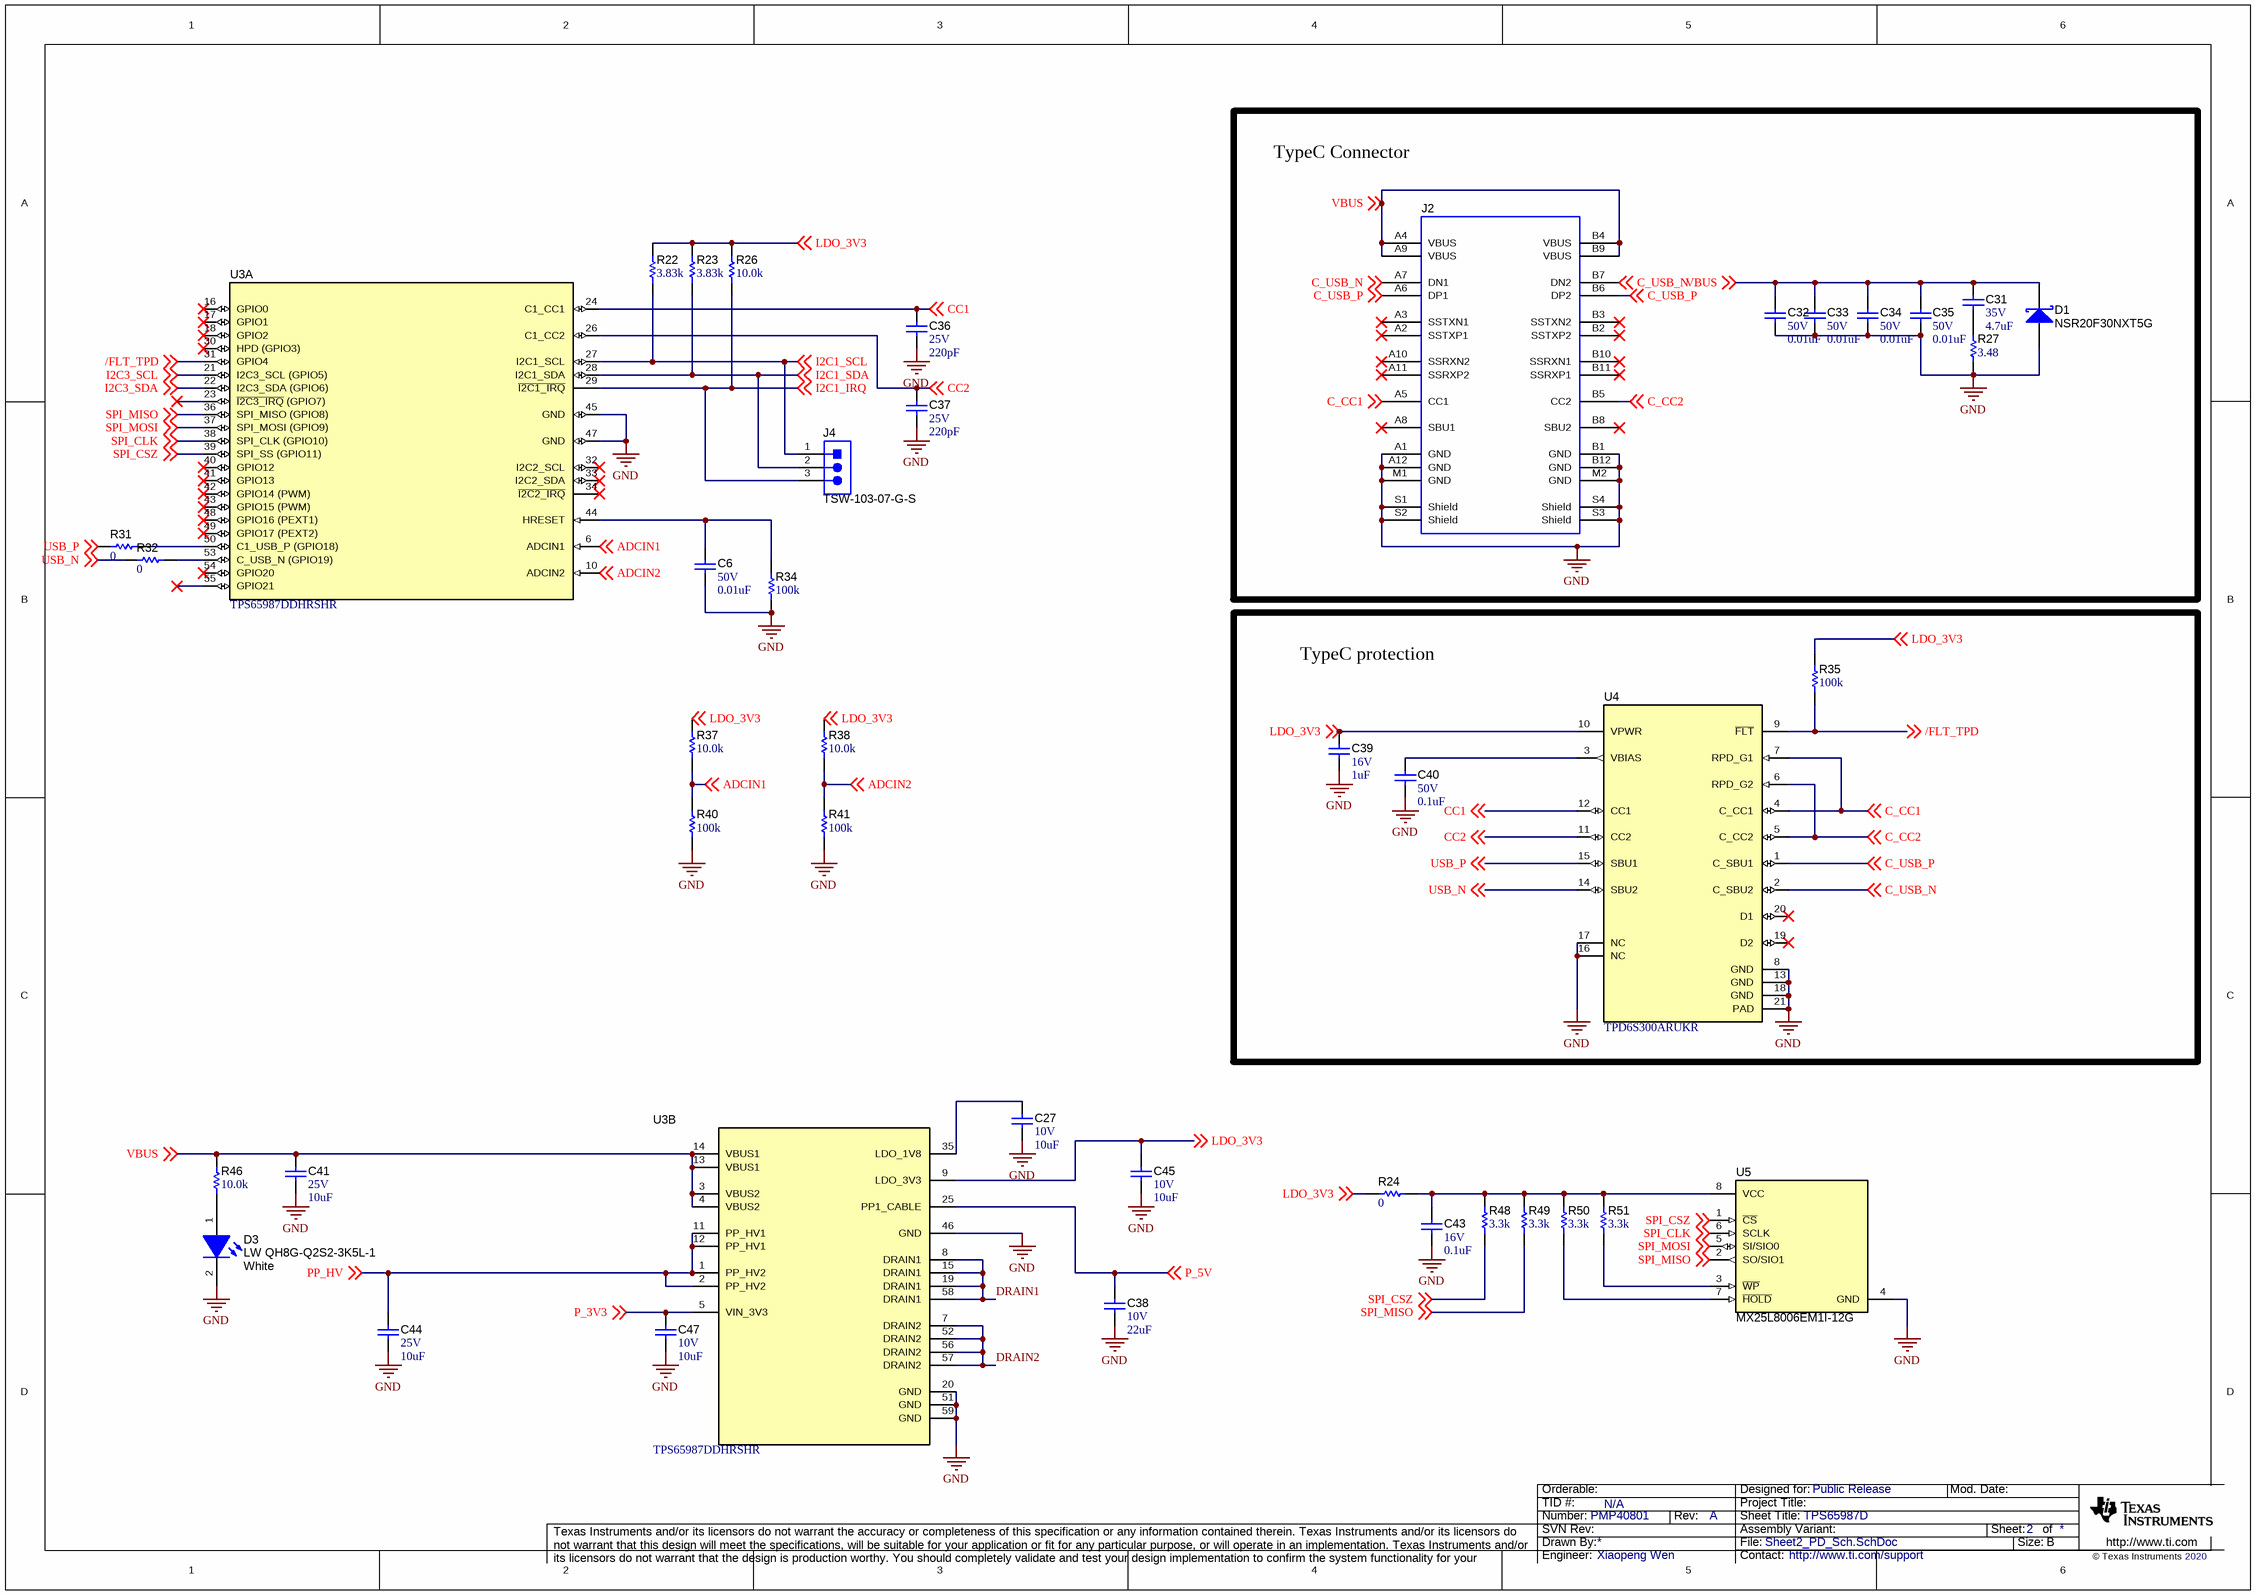
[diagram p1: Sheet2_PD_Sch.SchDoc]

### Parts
C6  VDC_V: 50V  ValueDisplayed: 0.01uF  [0402]  (hidden comment: GCM155R71H103KA55D)
C27  VDC_V: 10V  ValueDisplayed: 10uF  [0402_070]  (hidden comment: CL05A106MP5NUNC)
C31  VDC_V: 35V  ValueDisplayed: 4.7uF  [0603]  (hidden comment: GRM188R6YA475KE15D)
C32  VDC_V: 50V  ValueDisplayed: 0.01uF  [0402]  (hidden comment: GCM155R71H103KA55D)
C33  VDC_V: 50V  ValueDisplayed: 0.01uF  [0402]  (hidden comment: GCM155R71H103KA55D)
C34  VDC_V: 50V  ValueDisplayed: 0.01uF  [0402]  (hidden comment: GCM155R71H103KA55D)
C35  VDC_V: 50V  ValueDisplayed: 0.01uF  [0402]  (hidden comment: GCM155R71H103KA55D)
C36  VDC_V: 25V  ValueDisplayed: 220pF  [0201]  (hidden comment: GRM033R71E221KA01D)
C37  VDC_V: 25V  ValueDisplayed: 220pF  [0201]  (hidden comment: GRM033R71E221KA01D)
C38  VDC_V: 10V  ValueDisplayed: 22uF  [0603]  (hidden comment: C1608X5R1A226M080AC)
C39  VDC_V: 16V  ValueDisplayed: 1uF  [0402]  (hidden comment: EMK105BJ105KVHF)
C40  VDC_V: 50V  ValueDisplayed: 0.1uF  [0402]  (hidden comment: GCM155R71H104KE02D)
C41  VDC_V: 25V  ValueDisplayed: 10uF  [0603]  (hidden comment: GRM188R61E106MA73D)
C43  VDC_V: 16V  ValueDisplayed: 0.1uF  [0402]  (hidden comment: 885012205037)
C44  VDC_V: 25V  ValueDisplayed: 10uF  [0603]  (hidden comment: GRM188R61E106MA73D)
C45  VDC_V: 10V  ValueDisplayed: 10uF  [0402_070]  (hidden comment: CL05A106MP5NUNC)
C47  VDC_V: 10V  ValueDisplayed: 10uF  [0402_070]  (hidden comment: CL05A106MP5NUNC)
D1  NSR20F30NXT5G  [DSN2_0603]
D3  LW QH8G-Q2S2-3K5L-1  value White  [LW QH8G_White]
J2  632723300011  [Wurth_632_723_300_011]  (value not drawn)
J4  TSW-103-07-G-S  [TSW-103-07-G-S]
R22  ValueDisplayed: 3.83k  [0402]  (hidden comment: CRCW04023K83FKED)
R23  ValueDisplayed: 3.83k  [0402]  (hidden comment: CRCW04023K83FKED)
R24  ValueDisplayed: 0  [0201]  (hidden comment: CRCW02010000Z0ED)
R26  ValueDisplayed: 10.0k  [0402]  (hidden comment: ERJ-2RKF1002X)
R27  ValueDisplayed: 3.48  [0402]  (hidden comment: CRCW04023R48FKED)
R31  ValueDisplayed: 0  [0201]  (hidden comment: CRCW02010000Z0ED)
R32  ValueDisplayed: 0  [0201]  (hidden comment: CRCW02010000Z0ED)
R34  ValueDisplayed: 100k  [0402]  (hidden comment: CRCW0402100KFKED)
R35  ValueDisplayed: 100k  [0201]  (hidden comment: RC0201JR-7D100KL)
R37  ValueDisplayed: 10.0k  [0402]  (hidden comment: ERJ-2RKF1002X)
R38  ValueDisplayed: 10.0k  [0402]  (hidden comment: ERJ-2RKF1002X)
R40  ValueDisplayed: 100k  [0402]  (hidden comment: CRCW0402100KFKED)
R41  ValueDisplayed: 100k  [0402]  (hidden comment: CRCW0402100KFKED)
R46  ValueDisplayed: 10.0k  [0402]  (hidden comment: ERJ-2RKF1002X)
R48  ValueDisplayed: 3.3k  [0402]  (hidden comment: CRCW04023K30JNED)
R49  ValueDisplayed: 3.3k  [0402]  (hidden comment: CRCW04023K30JNED)
R50  ValueDisplayed: 3.3k  [0402]  (hidden comment: CRCW04023K30JNED)
R51  ValueDisplayed: 3.3k  [0402]  (hidden comment: CRCW04023K30JNED)
U3  TPS65987DDHRSHR  [RSH0056E]  (parts A,B of 2)
U4  TPD6S300ARUKR  [RUK0020B]
U5  MX25L8006EM1I-12G  [SOP-8_150MIL]

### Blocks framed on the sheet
TypeC Connector: C31-C35 D1 J2 R27
TypeC protection: C39 C40 R35 U4

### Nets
GND: C6.2 C27.2 C32.2 C33.2 C34.2 C35.2 C36.2 C37.2 C38.2 C39.2 C40.2 C41.2 C43.2 C44.2 C45.2 C47.2 D1.2(A) D3.2(K) J2.A1(GND) J2.A12(GND) J2.B1(GND) J2.B12(GND) J2.M1(GND) J2.M2(GND) J2.S1(Shield) J2.S2(Shield) J2.S3(Shield) J2.S4(Shield) R27.1 R34.1 R40.1 R41.1 U3.20(GND) U3.45(GND) U3.46(GND) U3.47(GND) U3.51(GND) U3.59(GND) U4.8(GND) U4.13(GND) U4.16(NC) U4.17(NC) U4.18(GND) U4.21(PAD) U5.4(GND)
/FLT_TPD: R35.1 U3.31(GPIO4) U4.9(~{FLT}) ; off-sheet /FLT_TPD
ADCIN1: R37.1 R40.2 U3.6(ADCIN1) ; off-sheet ADCIN1
ADCIN2: R38.1 R41.2 U3.10(ADCIN2) ; off-sheet ADCIN2
C_CC1: J2.A5(CC1) U4.4(C_CC1) U4.7(RPD_G1) ; off-sheet C_CC1
C_CC2: J2.B5(CC2) U4.5(C_CC2) U4.6(RPD_G2) ; off-sheet C_CC2
C_USB_N: J2.A7(DN1) J2.B7(DN2) U4.2(C_SBU2) ; off-sheet C_USB_N
C_USB_P: J2.A6(DP1) J2.B6(DP2) U4.1(C_SBU1) ; off-sheet C_USB_P
CC1: C36.1 U3.24(C1_CC1) U4.12(CC1) ; off-sheet CC1
CC2: C37.1 U3.26(C1_CC2) U4.11(CC2) ; off-sheet CC2
DRAIN1: U3.8(DRAIN1) U3.15(DRAIN1) U3.19(DRAIN1) U3.58(DRAIN1)
DRAIN2: U3.7(DRAIN2) U3.52(DRAIN2) U3.56(DRAIN2) U3.57(DRAIN2)
I2C1_IRQ: J4.3 R26.1 U3.29(~{I2C1_IRQ}) ; off-sheet I2C1_IRQ
I2C1_SCL: J4.1 R22.1 U3.27(I2C1_SCL) ; off-sheet I2C1_SCL
I2C1_SDA: J4.2 R23.1 U3.28(I2C1_SDA) ; off-sheet I2C1_SDA
I2C3_SCL: U3.21(I2C3_SCL_(GPIO5)) ; off-sheet I2C3_SCL
I2C3_SDA: U3.22(I2C3_SDA_(GPIO6)) ; off-sheet I2C3_SDA
LDO_3V3: C39.1 C45.1 R22.2 R23.2 R24.1 R26.2 R35.2 R37.2 R38.2 U3.9(LDO_3V3) U4.10(VPWR) ; off-sheet LDO_3V3
P_3V3: C47.1 U3.5(VIN_3V3) ; off-sheet P_3V3
P_5V: C38.1 U3.25(PP1_CABLE) ; off-sheet P_5V
PP_HV: C44.1 U3.1(PP_HV2) U3.2(PP_HV2) U3.11(PP_HV1) U3.12(PP_HV1) ; off-sheet PP_HV
SPI_CLK: U3.38(SPI_CLK_(GPIO10)) U5.6(SCLK) ; off-sheet SPI_CLK
SPI_CSZ: R48.1 U3.39(SPI_SS_(GPIO11)) U5.1(~{CS}) ; off-sheet SPI_CSZ
SPI_MISO: R49.1 U3.36(SPI_MISO_(GPIO8)) U5.2(SO/SIO1) ; off-sheet SPI_MISO
SPI_MOSI: U3.37(SPI_MOSI_(GPIO9)) U5.5(SI/SIO0) ; off-sheet SPI_MOSI
USB_N: R32.1 U4.14(SBU2) ; off-sheet USB_N
USB_P: R31.1 U4.15(SBU1) ; off-sheet USB_P
VBUS: C31.1 C32.1 C33.1 C34.1 C35.1 C41.1 D1.1(K) J2.A4(VBUS) J2.A9(VBUS) J2.B4(VBUS) J2.B9(VBUS) R46.2 U3.3(VBUS2) U3.4(VBUS2) U3.13(VBUS1) U3.14(VBUS1) ; off-sheet VBUS
NetC6_1: C6.1 R34.2 U3.44(HRESET)
NetC27_1: C27.1 U3.35(LDO_1V8)
NetC31_2: C31.2 R27.2
NetC40_1: C40.1 U4.3(VBIAS)
NetC43_1: C43.1 R24.2 R48.2 R49.2 R50.2 R51.2 U5.8(VCC)
NetD3_1: D3.1(A) R46.1
NetR31_2: R31.2 U3.50(C1_USB_P_(GPIO18))
NetR32_2: R32.2 U3.53(C_USB_N_(GPIO19))
NetR50_1: R50.1 U5.7(~{HOLD})
NetR51_1: R51.1 U5.3(~{WP})

Not connected (* = marked no-connect by the designer): J2 A2(SSTXP1)* A3(SSTXN1)* A8(SBU1)* A10(SSRXN2)* A11(SSRXP2)* B2(SSTXP2)* B3(SSTXN2)* B8(SBU2)* B10(SSRXN1)* B11(SSRXP1)*; U3 16(GPIO0)* 17(GPIO1)* 18(GPIO2)* 23(~{I2C3_IRQ}_(GPIO7))* 30(HPD_(GPIO3))* 32(I2C2_SCL)* 33(I2C2_SDA)* 34(~{I2C2_IRQ})* 40(GPIO12)* 41(GPIO13)* 42(GPIO14_(PWM))* 43(GPIO15_(PWM))* 48(GPIO16_(PEXT1))* 49(GPIO17_(PEXT2))* 54(GPIO20)* 55(GPIO21)*; U4 19(D2)* 20(D1)*

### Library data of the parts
C6 C32-C35 = CMP-0006355-2: CAP, CERM, 0.01 uF, 50 V, +/- 10%, C0G/NP0, 0402; Manufacturer: MuRata; TaMin_C: -55°C; Polarized: N; SizeAreaWB_mm2: 3; Value1: Unknown; U/M: EA; Value: 0.01uF; TaMax_C: 125°C; SizeZ_mm: 0.6; SizeX_mm: 1; SizeY_mm: 0.5; Cap_F: 10nF; AEC Category: Q200
C27 C45 C47 = CMP-0006339-4: CAP, CERM, 10 uF, 10 V, +/- 20%, X5R, 0402; Manufacturer: Samsung Electro-Mechanics; TaMin_C: -55°C; Polarized: N; SizeAreaWB_mm2: 3; Value1: Unknown; U/M: EA; Value: 10uF; TaMax_C: 85°C; SizeZ_mm: 0.6; SizeX_mm: 1; SizeY_mm: 0.5; Cap_Case: 0402; Cap_F: 10µF; AEC Category: Q200
C31 = CMP-0007357-5: CAP, CERM, 4.7 uF, 35 V, +/- 10%, X5R, 0603; Manufacturer: MuRata; TaMin_C: -55°C; Polarized: N; SizeAreaWB_mm2: 4.68; Value1: Unknown; U/M: EA; Value: 4.7uF; TaMax_C: 85°C; SizeZ_mm: 1; SizeX_mm: 1.6; SizeY_mm: 0.8; SizeArea_mm2: 1.28; Cap_F: 4.7µF; AEC Category: Q200
C36 C37 = CMP-0009770-1: CAP, CERM, 220 pF, 25 V, +/- 10%, X7R, 0201; Manufacturer: MuRata; TaMin_C: -55°C; Polarized: N; SizeAreaWB_mm2: 2.08; Value1: Unknown; U/M: EA; Value: 220pF; TaMax_C: 125°C; SizeZ_mm: 0.26; SizeX_mm: 0.6; SizeY_mm: 0.3; SizeArea_mm2: 0.18; AEC Category: Q200
C38 = CMP-0007005-5: CAP, CERM, 22 uF, 10 V, +/- 20%, X5R, 0603; Manufacturer: TDK; TaMin_C: -55°C; ESR_ohm: 3.71m; Polarized: N; SizeAreaWB_mm2: 4.68; Value1: 0.00371 ohm; U/M: EA; Value: 22uF; TaMax_C: 85°C; SizeZ_mm: 1; SizeX_mm: 1.6; SizeY_mm: 0.8; SizeArea_mm2: 1.28; Cap_F: 22µF; IRMS_A: 2.69936A; AEC Category: Q200
C39 = CMP-0006347-2: CAP, CERM, 1 uF, 16 V, +/- 10%, X5R, 0402; Manufacturer: Taiyo Yuden; TaMin_C: -55°C; Polarized: N; SizeAreaWB_mm2: 3; Value1: Unknown; U/M: EA; Value: 1uF; TaMax_C: 85°C; SizeZ_mm: 0.6; SizeX_mm: 1; SizeY_mm: 0.5; Cap_F: 1µF; AEC Category: Q200
C40 = CMP-0006356-2: as C23 on sheet Sheet1_Power_Sch
C41 C44 = CMP-0007344-5: CAP, CERM, 10 uF, 25 V, +/- 20%, X5R, 0603; Manufacturer: MuRata; TaMin_C: -55°C; Polarized: N; SizeAreaWB_mm2: 4.68; Value1: Unknown; U/M: EA; Value: 10uF; TaMax_C: 85°C; SizeZ_mm: 1; SizeX_mm: 1.6; SizeY_mm: 0.8; SizeArea_mm2: 1.28; Cap_F: 10µF; AEC Category: Q200
C43 = CMP-0006228-2: CAP, CERM, 0.1 uF, 16 V, +/- 10%, X7R, 0402; Manufacturer: Wurth Elektronik; TaMin_C: -55°C; Polarized: N; SizeAreaWB_mm2: 3; Value1: Unknown; U/M: EA; Value: 0.1uF; TaMax_C: 125°C; SizeZ_mm: 0.6; SizeX_mm: 1; SizeY_mm: 0.5; Cap_F: 100nF; AEC Category: Q200
D1 = CMP-0028829-2: Diode, Schottky, 30 V, 2 A, 2-XFDFN; Manufacturer: ON Semiconductor; Value2: 0.48V; SizeY_mm: 0.8; Value: 30V; TJmax_C: 150°C; Green_Lifecycle: Not Set; SizeAreaWB_mm2: 4.68; Value1: 2A; SizeArea_mm2: 1.28; Green_REACh: Incomplete; AEC Category: Q101; SizeZ_mm: 0.31; Vf_V: 4.8dV; AEC Qualified: N; SizeX_mm: 1.6
D3 = CMP-0002919-2: LED, White, SMD; Manufacturer: OSRAM; Value2: 2.8V; Angle: 120; Value1: W; Vr_V: 5V; Ir_A: 10nA; Tjmax_C: 95°C; Io_A: 5mA
J2 = CMP-0080891-1: Connector, Receptacle, USB Type C, R/A; Manufacturer: Wurth Elektronik; Current_A: 3A; Gender: Female; Voltage_V: 5V; ContactFinish: Gold; Cert_UL: Y
J4 = CMP-0075407-2: Header, 100mil, 3x1, Gold, TH; Manufacturer: Samtec; Pitch_mm: 2.54; Cert_VDE: N; Gender: Male; Cert_CSA: Y; Voltage_V: 550V; Green_REACh: Passed; Current_A: 6.3A; Green_Lifecycle: Active; Row_Count: 1
R22 R23 = CMP-0026339-2: RES, 3.83 k, 1%, 0.063 W, AEC-Q200 Grade 0, 0402; Manufacturer: Vishay-Dale; Power_W: 63mW; TempCo: 100 ppm/C; Value_Code: 3k83; Value: 3.83k; EIA_Code: E96; SizeX_mm: 1; SizeY_mm: 0.5; SizeZ_mm: 0.6; Value2: 0.063W; AEC Qualified: Y; VDC_V: 50V; AEC Category: Q200; AEC Grade: 0
R24 R31 R32 = CMP-0027008-4: RES, 0, 5%, 0.05 W, 0201; Manufacturer: Vishay-Dale; Power_W: 50mW; TempCo: ppm/C; Value_Code: 0000; Value: 0; EIA_Code: E24; SizeX_mm: 0.6; SizeY_mm: 0.3; SizeZ_mm: 0.26; Value2: 0.05W; SizeArea_mm2: 0.18; AEC Qualified: N; AEC Category: Q200
R26 R37 R38 R46 = CMP-0026658-1: RES, 10.0 k, 1%, 0.1 W, 0402; Manufacturer: Panasonic; Power_W: 100mW; TempCo: 100 ppm/C; Value_Code: 10k0; U/M: EA; Value: 10.0k; EIA_Code: E96; Res_ohm: 10k; SizeX_mm: 1; SizeY_mm: 0.5; SizeZ_mm: 0.6; Value2: 0.1W; VDC_V: 50V; AEC Category: Q200
R27 = CMP-0026359-2: RES, 3.48, 1%, 0.063 W, AEC-Q200 Grade 0, 0402; Manufacturer: Vishay-Dale; Power_W: 63mW; TempCo: 100 ppm/C; Value_Code: 3R48; Value: 3.48; EIA_Code: E96; SizeX_mm: 1; SizeY_mm: 0.5; SizeZ_mm: 0.6; Value2: 0.063W; AEC Qualified: Y; VDC_V: 50V; AEC Category: Q200; AEC Grade: 0
R34 R40 R41 = CMP-0025950-3: RES, 100 k, 1%, 0.063 W, AEC-Q200 Grade 0, 0402; Manufacturer: Vishay-Dale; Power_W: 63mW; TempCo: 100 ppm/C; Value: 100k; EIA_Code: E96; SizeX_mm: 1; SizeY_mm: 0.5; SizeZ_mm: 0.6; Value2: 0.063W; AEC Qualified: Y; VDC_V: 50V; AEC Category: Q200; AEC Grade: 0
R35 = CMP-0027184-1: RES, 100 k, 5%, 0.05 W, 0201; Manufacturer: Yageo America; Power_W: 50mW; TempCo: 200 ppm/C; U/M: EA; Value: 100k; EIA_Code: E24; SizeX_mm: 0.6; SizeY_mm: 0.3; SizeZ_mm: 0.26; Value2: 0.05W; SizeArea_mm2: 0.18; AEC Qualified: N; VDC_V: 25V; AEC Category: Q200
R48-R51 = CMP-0026918-5: RES, 3.3 k, 5%, 0.063 W, AEC-Q200 Grade 0, 0402; Manufacturer: Vishay-Dale; Power_W: 63mW; TempCo: 200 ppm/C; Value_Code: 3k30; Value: 3.3k; EIA_Code: E24; SizeX_mm: 1; SizeY_mm: 0.5; SizeZ_mm: 0.6; Value2: 0.063W; AEC Qualified: Y; VDC_V: 50V; AEC Category: Q200; AEC Grade: 0
U3 = CMP-0081032-2: USB Type-C and USB PD Controller with Integrated Power Switches, RSH0056E (VQFN-56); Alternate PartNumber: TPS65987DDHRSHT; Alternate Manufacturer: Texas Instruments; SizeAreaWB_mm2: 81; SizeZ_mm: 1; SizeX_mm: 7; SizeArea_mm2: 49; CompType: IC; AEC Qualified: N; AEC Category: Q200
U4 = CMP-0081565-1: USB Type-C Port Protector: Short-to-VBUS Overvoltage and IEC ESD Protection, RUK0020B (WQFN-20); Alternate Manufacturer: Texas Instruments; SizeAreaWB_mm2: 16; SizeZ_mm: 0.8; SizeX_mm: 3; SizeArea_mm2: 9; CompType: IC; AEC Qualified: N; AEC Category: Q200
U5 = CMP-0078948-1: 8Mb, 86MHz, NOR Flash, SOP-8; Manufacturer: Macronix International Co., LTD

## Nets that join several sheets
GND: Sheet1_Power_Sch (39 pins), Sheet2_PD_Sch (45 pins)
I2C3_SCL: Sheet1_Power_Sch (J1.9 R9.1 U2.5), Sheet2_PD_Sch (U3.21)
I2C3_SDA: Sheet1_Power_Sch (J1.10 R10.1 U2.6), Sheet2_PD_Sch (U3.22)
LDO_3V3: Sheet1_Power_Sch (R9.2 R10.2), Sheet2_PD_Sch (11 pins)
P_3V3: Sheet1_Power_Sch (10 pins), Sheet2_PD_Sch (C47.1 U3.5)
P_5V: Sheet1_Power_Sch (C29.1 C30.1 U6.9), Sheet2_PD_Sch (C38.1 U3.25)
PP_HV: Sheet1_Power_Sch (C11.2 R8.2 U2.13), Sheet2_PD_Sch (5 pins)
SPI_CLK: Sheet1_Power_Sch (J1.8), Sheet2_PD_Sch (U3.38 U5.6)
SPI_CSZ: Sheet1_Power_Sch (J1.2), Sheet2_PD_Sch (R48.1 U3.39 U5.1)
SPI_MISO: Sheet1_Power_Sch (J1.3), Sheet2_PD_Sch (R49.1 U3.36 U5.2)
SPI_MOSI: Sheet1_Power_Sch (J1.4), Sheet2_PD_Sch (U3.37 U5.5)

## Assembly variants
001: not fitted C1 C5 C9 C10 C13 D1 FID1 FID2 FID3 FID4 FID5 FID6 R1 R2 R2 R8 R12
